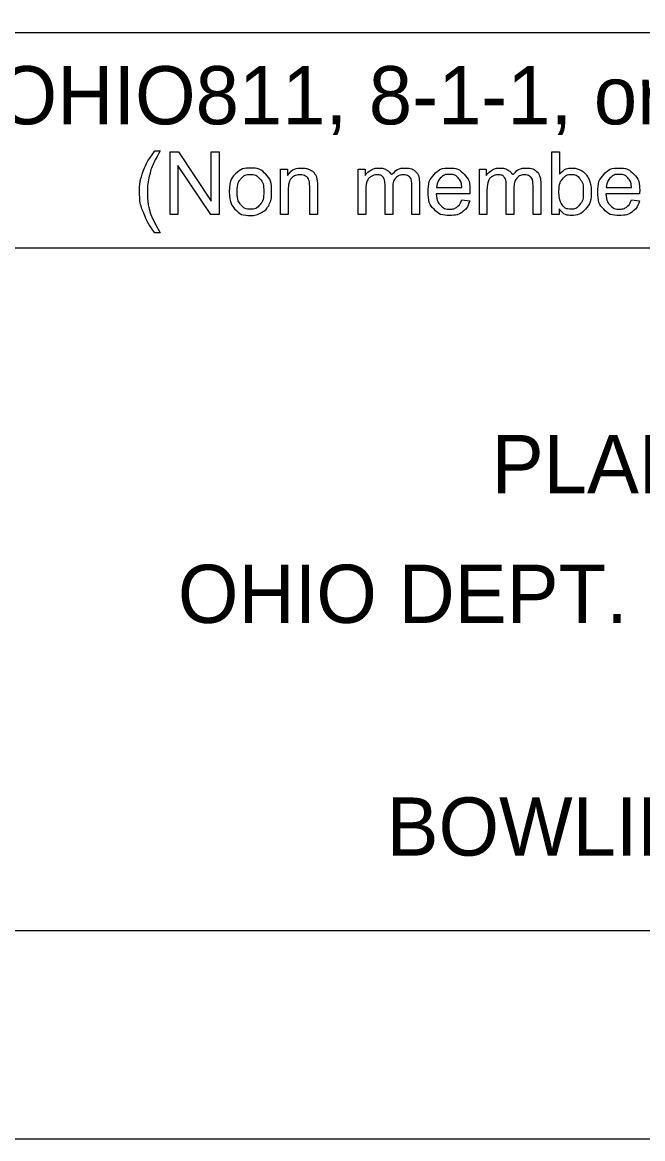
# Model space of a CAD drawing. Extents: x -5.6 to 34, y 0 to 22.
# Drawn here: x 3.084 to 4.575, y 0 to 2.686 of the extents above; entities that cross this region are included whole.
import ezdxf

# ---------------------------------------------------------------- set-up
doc = ezdxf.new("R2010")
doc.units = 0
for name, color, linetype in [('SH_Border', 7, 'Continuous'), ('SH_Cut_Line', 7, 'Continuous'), ('SH_Data', 7, 'Continuous'), ('SH_Text', 7, 'Continuous')]:
    doc.layers.add(name, color=color, linetype=linetype)

msp = doc.modelspace()

# ---------------------------------------------------------------- linework, layer by layer
at = {"layer": 'SH_Border'}
msp.add_lwpolyline([(1.5, 21.5), (33.5, 21.5), (33.5, 0.5), (1.5, 0.5)], close=True, dxfattribs=at)
at = {"layer": 'SH_Cut_Line'}
msp.add_lwpolyline([(0, 0), (34, 0), (34, 22), (0, 22)], close=True, dxfattribs=at)
at = {"layer": 'SH_Data'}
for p, q in [((7.2275, 2.6607), (2.9775, 2.6607)), ((7.2275, 2.1428), (2.9775, 2.1428))]:
    msp.add_line(p, q, dxfattribs=at)
at = {"layer": 'SH_Text'}
for points in [[(3.4021, 2.3766), (3.4153, 2.3766)], [(3.4389, 2.2239), (3.4389, 2.3741), (3.4592, 2.3741), (3.5382, 2.2561), (3.5382, 2.3741), (3.5572, 2.3741), (3.5572, 2.2239), (3.5369, 2.2239), (3.4579, 2.3419), (3.4579, 2.2239), (3.4389, 2.2239)], [(4.3743, 2.2239), (4.3573, 2.2239), (4.3573, 2.3741), (4.3757, 2.3741), (4.3757, 2.3206)], [(3.7048, 2.2239), (3.7048, 2.3328), (3.7214, 2.3328), (3.7214, 2.3173)], [(3.8912, 2.2239), (3.8912, 2.3328), (3.9077, 2.3328), (3.9077, 2.3174)], [(4.1826, 2.2239), (4.1826, 2.3328), (4.1991, 2.3328), (4.1991, 2.3174)], [(3.7233, 2.2833), (3.7233, 2.2239), (3.7048, 2.2239)], [(3.7932, 2.2908), (3.7932, 2.2239), (3.7748, 2.2239), (3.7748, 2.2901)], [(3.9743, 2.2871), (3.9743, 2.2239), (3.9559, 2.2239), (3.9559, 2.2946)], [(4.0388, 2.2986), (4.0388, 2.2239), (4.0203, 2.2239), (4.0203, 2.2924)], [(4.0799, 2.2887), (4.1406, 2.2887)], [(4.2657, 2.2871), (4.2657, 2.2239), (4.2473, 2.2239), (4.2473, 2.2946)], [(4.3301, 2.2986), (4.3301, 2.2239), (4.3117, 2.2239), (4.3117, 2.2924)], [(4.4879, 2.2887), (4.5486, 2.2887)], [(3.9097, 2.2803), (3.9097, 2.2239), (3.8912, 2.2239)], [(4.16, 2.2736), (4.0788, 2.2736)], [(4.1404, 2.2591), (4.1595, 2.2567)], [(4.201, 2.2803), (4.201, 2.2239), (4.1826, 2.2239)], [(4.568, 2.2736), (4.4868, 2.2736)], [(4.5484, 2.2591), (4.5675, 2.2567)], [(4.3743, 2.2375), (4.3743, 2.2239)], [(3.4153, 2.1798), (3.4021, 2.1798)]]:
    msp.add_lwpolyline(points, dxfattribs=at)
for points in [[(3.4021, 2.1798), (3.3869, 2.199), (3.3763, 2.2248), (3.3657, 2.2506), (3.3657, 2.2783), (3.3657, 2.3026), (3.3736, 2.325), (3.3829, 2.3509), (3.4021, 2.3766)], [(3.4153, 2.3766), (3.4029, 2.3553), (3.3989, 2.3462), (3.3927, 2.332), (3.3891, 2.3167), (3.3847, 2.2975), (3.3847, 2.2782), (3.3847, 2.2289), (3.4153, 2.1798)], [(3.5814, 2.2783), (3.5814, 2.3085), (3.5981, 2.3231), (3.6122, 2.3352), (3.6323, 2.3352), (3.6547, 2.3352), (3.669, 2.3205), (3.6832, 2.3058), (3.6832, 2.2799), (3.6832, 2.2589), (3.6769, 2.2469), (3.6706, 2.2348), (3.6586, 2.2282), (3.6466, 2.2215), (3.6323, 2.2215), (3.6095, 2.2215), (3.5954, 2.2362), (3.5814, 2.2508), (3.5814, 2.2783)], [(3.6003, 2.2783), (3.6003, 2.2574), (3.6094, 2.247), (3.6185, 2.2366), (3.6323, 2.2366), (3.646, 2.2366), (3.6551, 2.2471), (3.6642, 2.2575), (3.6642, 2.279), (3.6642, 2.2991), (3.6551, 2.3095), (3.6459, 2.3199), (3.6323, 2.3199), (3.6185, 2.3199), (3.6094, 2.3096), (3.6003, 2.2992), (3.6003, 2.2783)], [(3.7214, 2.3173), (3.7334, 2.3352), (3.756, 2.3352), (3.7659, 2.3352), (3.7741, 2.3316), (3.7823, 2.3281), (3.7864, 2.3224), (3.7905, 2.3166), (3.7922, 2.3087), (3.7932, 2.3036), (3.7932, 2.2908)], [(3.7748, 2.2901), (3.7748, 2.3013), (3.7726, 2.3069), (3.7705, 2.3125), (3.765, 2.3158), (3.7595, 2.3191), (3.7521, 2.3191), (3.7404, 2.3191), (3.7318, 2.3117), (3.7233, 2.3042), (3.7233, 2.2833)], [(3.9077, 2.3174), (3.9128, 2.3254), (3.9214, 2.3303), (3.9299, 2.3352), (3.9407, 2.3352), (3.9528, 2.3352), (3.9606, 2.3301), (3.9683, 2.3251), (3.9715, 2.3161), (3.9844, 2.3352), (4.0051, 2.3352), (4.0213, 2.3352), (4.03, 2.3262), (4.0388, 2.3172), (4.0388, 2.2986)], [(3.9559, 2.2946), (3.9559, 2.3069), (3.9514, 2.313), (3.9469, 2.3191), (3.9366, 2.3191), (3.9288, 2.3191), (3.9222, 2.315), (3.9156, 2.311), (3.9126, 2.3031), (3.9097, 2.2952), (3.9097, 2.2803)], [(4.0203, 2.2924), (4.0203, 2.3035), (4.0185, 2.3083), (4.0168, 2.3132), (4.012, 2.3162), (4.0073, 2.3191), (4.001, 2.3191), (3.9895, 2.3191), (3.9819, 2.3115), (3.9743, 2.3039), (3.9743, 2.2871)], [(4.1595, 2.2567), (4.155, 2.24), (4.1428, 2.2307), (4.1306, 2.2215), (4.1117, 2.2215), (4.0878, 2.2215), (4.0738, 2.2362), (4.0598, 2.2509), (4.0598, 2.2774), (4.0598, 2.3049), (4.074, 2.32), (4.0881, 2.3352), (4.1106, 2.3352), (4.1324, 2.3352), (4.1463, 2.3203), (4.1601, 2.3055), (4.1601, 2.2785), (4.1601, 2.2769), (4.16, 2.2736)], [(4.1406, 2.2887), (4.1394, 2.3025), (4.1337, 2.3094), (4.1249, 2.3201), (4.1108, 2.3201), (4.0981, 2.3201), (4.0894, 2.3115), (4.0808, 2.303), (4.0799, 2.2887)], [(4.1991, 2.3174), (4.2042, 2.3254), (4.2127, 2.3303), (4.2212, 2.3352), (4.2321, 2.3352), (4.2442, 2.3352), (4.2519, 2.3301), (4.2597, 2.3251), (4.2628, 2.3161), (4.2758, 2.3352), (4.2965, 2.3352), (4.3127, 2.3352), (4.3214, 2.3262), (4.3301, 2.3172), (4.3301, 2.2986)], [(4.2473, 2.2946), (4.2473, 2.3069), (4.2428, 2.313), (4.2383, 2.3191), (4.228, 2.3191), (4.2202, 2.3191), (4.2136, 2.315), (4.207, 2.311), (4.204, 2.3031), (4.201, 2.2952), (4.201, 2.2803)], [(4.3117, 2.2924), (4.3117, 2.3035), (4.3099, 2.3083), (4.3081, 2.3132), (4.3034, 2.3162), (4.2987, 2.3191), (4.2923, 2.3191), (4.2809, 2.3191), (4.2733, 2.3115), (4.2657, 2.3039), (4.2657, 2.2871)], [(4.3741, 2.2792), (4.3741, 2.2596), (4.3794, 2.2509), (4.3881, 2.2366), (4.4029, 2.2366), (4.415, 2.2366), (4.4238, 2.2471), (4.4326, 2.2576), (4.4326, 2.2784), (4.4326, 2.2998), (4.4241, 2.3099), (4.4157, 2.3201), (4.4038, 2.3201), (4.3917, 2.3201), (4.3829, 2.3096), (4.3741, 2.299), (4.3741, 2.2792)], [(4.3757, 2.3206), (4.3874, 2.3352), (4.4055, 2.3352), (4.4155, 2.3352), (4.4245, 2.3311), (4.4335, 2.3271), (4.4392, 2.3198), (4.445, 2.3124), (4.4483, 2.3021), (4.4516, 2.2918), (4.4516, 2.28), (4.4516, 2.252), (4.4378, 2.2368), (4.4239, 2.2215), (4.4046, 2.2215), (4.3853, 2.2215), (4.3743, 2.2375)], [(4.5675, 2.2567), (4.563, 2.24), (4.5508, 2.2307), (4.5386, 2.2215), (4.5196, 2.2215), (4.4958, 2.2215), (4.4818, 2.2362), (4.4678, 2.2509), (4.4678, 2.2774), (4.4678, 2.3049), (4.482, 2.32), (4.4961, 2.3352), (4.5186, 2.3352), (4.5404, 2.3352), (4.5543, 2.3203), (4.5681, 2.3055), (4.5681, 2.2785), (4.5681, 2.2769), (4.568, 2.2736)], [(4.5486, 2.2887), (4.5474, 2.3025), (4.5417, 2.3094), (4.5328, 2.3201), (4.5188, 2.3201), (4.5061, 2.3201), (4.4974, 2.3115), (4.4888, 2.303), (4.4879, 2.2887)], [(4.0788, 2.2736), (4.0799, 2.2557), (4.089, 2.2462), (4.0981, 2.2366), (4.1117, 2.2366), (4.1219, 2.2366), (4.1291, 2.242), (4.1362, 2.2473), (4.1404, 2.2591)], [(4.4868, 2.2736), (4.4879, 2.2557), (4.497, 2.2462), (4.5061, 2.2366), (4.5197, 2.2366), (4.5299, 2.2366), (4.537, 2.242), (4.5442, 2.2473), (4.5484, 2.2591)]]:
    msp.add_open_spline(points, degree=3, dxfattribs=at)

# ---------------------------------------------------------------- texts
for s, p in [('OHIO811, 8-1-1, or 1-800-362-2764', (3.022, 2.4406)), ('PLAN PREPARED BY:', (4.2125, 1.553)), ('OHIO DEPT. OF TRANSPORTATION', (3.4578, 1.241)), ('BOWLING GREEN, OHIO', (3.9596, 0.681))]:
    msp.add_text(s, height=0.14, dxfattribs=at).set_placement(p)

doc.saveas('drawing.dxf')
